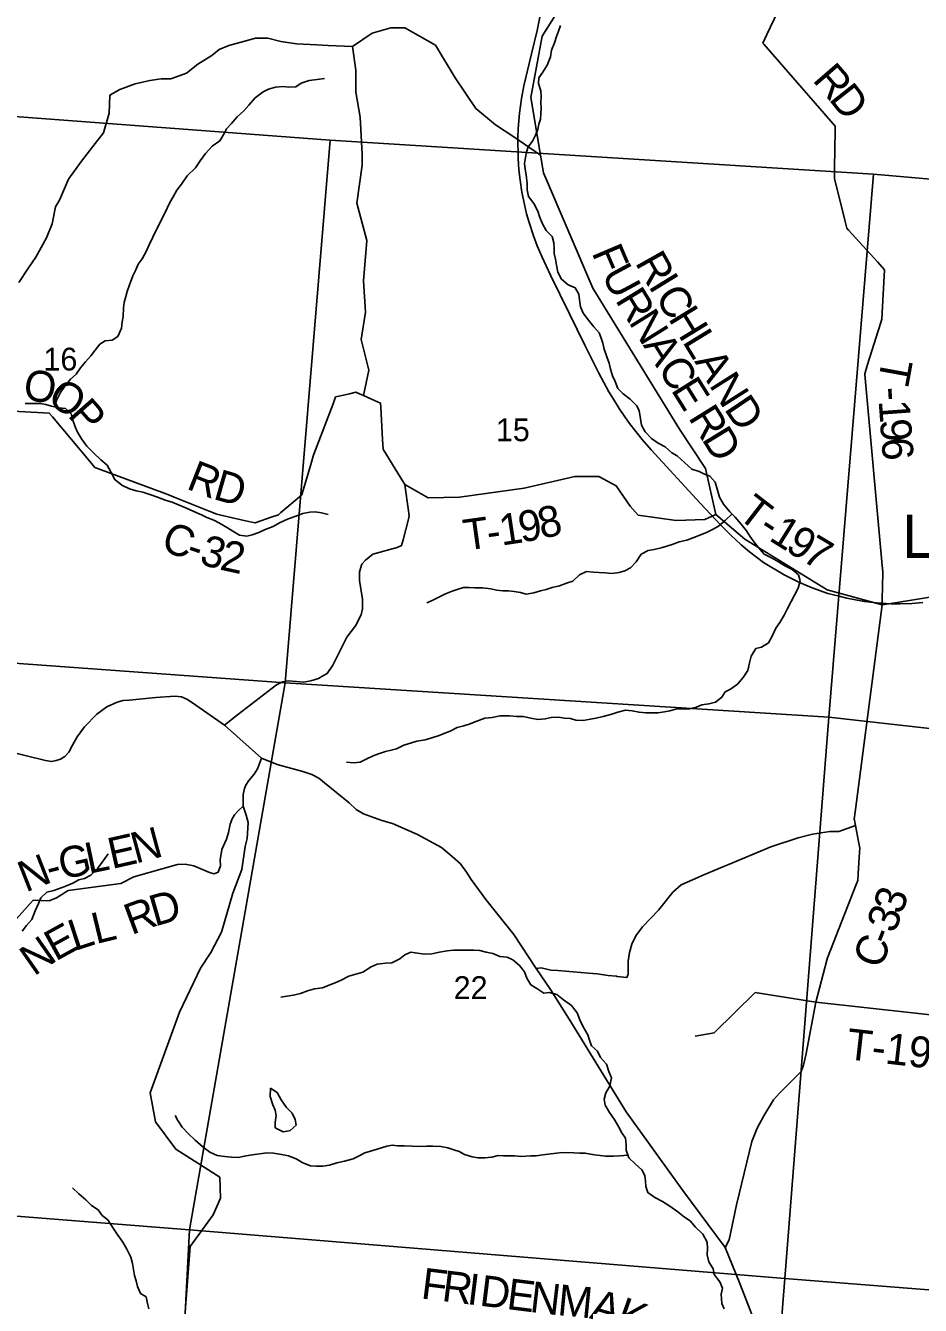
# Model space of a CAD drawing. Extents: x 1715311 to 2083412, y 146837 to 553079.
# Drawn here: x 1938656 to 1947326, y 414870 to 427271 of the extents above; entities that cross this region are included whole.
import ezdxf

# ---------------------------------------------------------------- set-up
doc = ezdxf.new("R2010")
doc.units = 0
for name, color, linetype in [('GM_X_County_Road', 7, 'Continuous'), ('GM_X_County_Road_Text', 7, 'Continuous'), ('GM_X_Minor_Lake', 7, 'Continuous'), ('GM_X_Minor_River', 7, 'Continuous'), ('GM_X_Rail_Line', 7, 'Continuous'), ('GM_X_Section', 7, 'Continuous'), ('GM_X_Section_Text', 7, 'Continuous'), ('GM_X_State_Route', 7, 'Continuous'), ('GM_X_Township_Road', 7, 'Continuous'), ('GM_X_Township_Road_Text', 7, 'Continuous'), ('GM_X_Township_ROW', 7, 'Continuous'), ('GM_X_Unincorporated_Text', 7, 'Continuous')]:
    doc.layers.add(name, color=color, linetype=linetype)

msp = doc.modelspace()

# ---------------------------------------------------------------- linework, layer by layer
at = {"layer": 'GM_X_County_Road'}
for points in [[(1940582, 420491), (1940708, 420592), (1941089, 420884), (1941146, 420914), (1941202, 420923), (1941280, 420915), (1941349, 420910), (1941421, 420923), (1941493, 420944), (1941542, 420974), (1941579, 420994), (1941634, 421073), (1941769, 421345), (1941853, 421456), (1941908, 421561), (1941918, 421608), (1941920, 421612), (1941920, 421712), (1941893, 421894), (1941893, 421978), (1941915, 422052), (1941949, 422091), (1942020, 422151), (1942256, 422215), (1942300, 422233), (1942314, 422288), (1942365, 422490), (1942372, 422521), (1942362, 422593), (1942334, 422800), (1942330, 422824), (1942288, 422892), (1942125, 423159), (1942120, 423166), (1942115, 423262), (1942098, 423574), (1942096, 423613), (1942036, 423639), (1941931, 423686), (1941893, 423703), (1941856, 423719), (1941794, 423704), (1941692, 423681), (1941660, 423673), (1941635, 423607), (1941449, 423119), (1941442, 423100), (1941419, 423019), (1941347, 422769), (1941334, 422726), (1941289, 422687), (1941130, 422552), (1941106, 422531), (1941037, 422507), (1940890, 422456), (1940882, 422453), (1940788, 422474), (1940534, 422532), (1940510, 422537), (1940436, 422567), (1940096, 422701), (1940050, 422720), (1939999, 422739), (1939364, 422976), (1939328, 422990), (1939286, 423040), (1938917, 423480), (1938886, 423517), (1938830, 423520), (1938413, 423541)], [(1947021, 421668), (1948875, 421968), (1949320, 421983), (1949558, 421879), (1950033, 421640), (1952911, 421117), (1953079, 421207), (1954316, 420828), (1954510, 421266), (1954816, 421770), (1955712, 421936), (1956245, 422267), (1957485, 422207), (1957564, 422217)], [(1945436, 415430), (1945472, 415507), (1945543, 415846), (1945693, 416458), (1945746, 416587), (1945809, 416706), (1945902, 416861), (1945962, 416927), (1946171, 417136), (1946194, 417199), (1946221, 417310), (1946314, 417807), (1946419, 418215), (1946425, 418239), (1946454, 418314), (1946705, 418950), (1946719, 418986), (1946723, 419052), (1946736, 419262), (1946739, 419301), (1946726, 419366), (1946697, 419521), (1946687, 419572), (1946685, 419583), (1946697, 419677), (1946956, 421658), (1947021, 421668)]]:
    msp.add_lwpolyline(points, dxfattribs=at)
at = {"layer": 'GM_X_Minor_Lake'}
for points in [[(1941030, 416975), (1941026, 416895), (1941051, 416813), (1941073, 416761), (1941085, 416711), (1941075, 416641), (1941075, 416591), (1941151, 416553), (1941191, 416560)], [(1941191, 416560), (1941221, 416565), (1941277, 416617), (1941269, 416671), (1941239, 416733), (1941183, 416787), (1941133, 416861), (1941094, 416933), (1941030, 416975)]]:
    msp.add_lwpolyline(points, dxfattribs=at)
at = {"layer": 'GM_X_Minor_River'}
for points in [[(1943839, 427273), (1943819, 427217), (1943799, 427165), (1943781, 427103), (1943751, 427033), (1943743, 426969), (1943711, 426889), (1943669, 426821), (1943629, 426765), (1943625, 426709), (1943650, 426640), (1943652, 426586), (1943648, 426524), (1943652, 426472), (1943648, 426416), (1943644, 426366), (1943630, 426316), (1943620, 426266), (1943598, 426210), (1943569, 426152), (1943525, 426096), (1943511, 426044), (1943501, 425994), (1943491, 425934), (1943497, 425880), (1943505, 425824), (1943515, 425742), (1943517, 425680), (1943528, 425614), (1943580, 425548), (1943620, 425474), (1943636, 425420), (1943664, 425349), (1943699, 425287), (1943759, 425227), (1943773, 425167), (1943779, 425113), (1943779, 425063), (1943791, 425007), (1943799, 424951), (1943813, 424881)], [(1938935, 423578), (1938956, 423638), (1938996, 423716), (1939037, 423778), (1939093, 423844), (1939145, 423894), (1939187, 423954), (1939237, 424014), (1939287, 424072), (1939329, 424126), (1939377, 424184), (1939427, 424216), (1939495, 424224), (1939551, 424260), (1939585, 424340), (1939593, 424400), (1939601, 424454), (1939605, 424538), (1939613, 424588), (1939626, 424646), (1939640, 424696), (1939662, 424760), (1939696, 424846), (1939724, 424904), (1939746, 424958), (1939786, 425010), (1939824, 425082), (1939854, 425146), (1939888, 425222), (1939927, 425302), (1939969, 425382), (1940029, 425502), (1940053, 425556), (1940087, 425613), (1940123, 425677), (1940167, 425735), (1940223, 425815), (1940301, 425893), (1940347, 425961), (1940401, 426033), (1940463, 426103), (1940537, 426153), (1940576, 426219), (1940602, 426271), (1940652, 426323), (1940706, 426387), (1940772, 426445), (1940820, 426501), (1940882, 426571), (1940958, 426630), (1941010, 426654), (1941078, 426674), (1941152, 426680), (1941206, 426676), (1941276, 426678), (1941326, 426712), (1941404, 426740), (1941483, 426749), (1941553, 426757)], [(1943813, 424881), (1943848, 424815), (1943914, 424760), (1943982, 424730), (1944018, 424670), (1944024, 424614), (1944034, 424546), (1944059, 424484), (1944111, 424418), (1944161, 424351), (1944215, 424293), (1944233, 424243), (1944249, 424193), (1944262, 424135), (1944288, 424063), (1944310, 424001), (1944324, 423943), (1944344, 423877), (1944368, 423821), (1944395, 423754), (1944445, 423702), (1944513, 423650), (1944577, 423590), (1944601, 423540), (1944613, 423460), (1944624, 423400), (1944658, 423335), (1944722, 423269), (1944786, 423225), (1944852, 423189), (1944917, 423133), (1944969, 423103), (1945113, 422974), (1945183, 422950), (1945235, 422926), (1945286, 422904), (1945338, 422848), (1945362, 422769), (1945380, 422701), (1945420, 422635), (1945481, 422561), (1945533, 422507), (1945589, 422439), (1945641, 422376), (1945673, 422324), (1945715, 422266), (1945754, 422216), (1945814, 422148), (1945884, 422114), (1945950, 422075), (1946018, 422033), (1946084, 422001), (1946145, 421949), (1946161, 421891), (1946141, 421819), (1946107, 421751), (1946073, 421691), (1946037, 421617), (1946005, 421559), (1945963, 421487), (1945927, 421431), (1945890, 421355), (1945856, 421289), (1945788, 421247), (1945732, 421235), (1945688, 421161), (1945672, 421097), (1945654, 421023), (1945608, 420955), (1945554, 420891), (1945486, 420843), (1945434, 420815), (1945404, 420763), (1945342, 420716), (1945278, 420698), (1945208, 420690), (1945156, 420668), (1945090, 420650), (1945038, 420648), (1944968, 420650), (1944898, 420630), (1944846, 420621), (1944782, 420611), (1944730, 420611), (1944667, 420613), (1944601, 420617), (1944535, 420631), (1944469, 420637), (1944395, 420620), (1944335, 420598), (1944253, 420576), (1944183, 420560), (1944129, 420552), (1944059, 420538), (1943989, 420542), (1943935, 420556), (1943876, 420559), (1943822, 420571), (1943750, 420567), (1943692, 420553), (1943620, 420549)], [(1938653, 423611), (1938727, 423609), (1938802, 423609), (1938854, 423600), (1938908, 423584), (1938978, 423568), (1939044, 423560), (1939098, 423508), (1939110, 423458), (1939138, 423382), (1939159, 423332), (1939197, 423267), (1939251, 423197), (1939313, 423131), (1939385, 423065)], [(1939385, 423065), (1939446, 423013), (1939484, 422940), (1939520, 422872), (1939590, 422818), (1939662, 422782), (1939728, 422762), (1939793, 422750), (1939869, 422725), (1939935, 422701), (1940017, 422669), (1940077, 422653), (1940137, 422627), (1940217, 422595), (1940286, 422562), (1940360, 422532), (1940414, 422506), (1940480, 422478), (1940534, 422450), (1940612, 422404), (1940665, 422371), (1940729, 422335), (1940799, 422325), (1940853, 422337), (1940915, 422361), (1940979, 422387), (1941055, 422419), (1941115, 422452), (1941195, 422490), (1941265, 422514), (1941343, 422544), (1941411, 422558), (1941463, 422560), (1941523, 422550), (1941587, 422533)], [(1945501, 422540), (1945435, 422475), (1945369, 422421), (1945311, 422389), (1945259, 422363), (1945189, 422333), (1945131, 422311), (1945063, 422286), (1944988, 422268), (1944920, 422244), (1944868, 422226), (1944816, 422212), (1944746, 422194), (1944690, 422184), (1944622, 422148), (1944572, 422076), (1944516, 422017), (1944462, 421987), (1944408, 421971), (1944336, 421963), (1944272, 421969), (1944210, 421971), (1944158, 421975), (1944090, 421981), (1944022, 421948), (1943960, 421888), (1943898, 421868), (1943830, 421844), (1943758, 421826), (1943700, 421806), (1943646, 421794), (1943582, 421774), (1943508, 421763), (1943451, 421779), (1943391, 421787), (1943335, 421793), (1943281, 421793), (1943219, 421801), (1943165, 421813), (1943085, 421824), (1943009, 421824), (1942953, 421826), (1942899, 421826), (1942847, 421810), (1942791, 421792), (1942726, 421764), (1942674, 421740), (1942596, 421702), (1942544, 421679)], [(1943620, 420549), (1943552, 420561), (1943476, 420578), (1943412, 420578), (1943344, 420584), (1943256, 420584), (1943178, 420568), (1943105, 420562), (1943027, 420530), (1942953, 420503), (1942901, 420487), (1942839, 420469), (1942769, 420433), (1942717, 420415), (1942663, 420391), (1942593, 420371), (1942527, 420351), (1942447, 420336), (1942395, 420320), (1942321, 420298), (1942249, 420264), (1942197, 420250), (1942143, 420236), (1942075, 420216), (1942023, 420194), (1941969, 420168), (1941897, 420133), (1941833, 420129), (1941767, 420135)], [(1938622, 418498), (1938664, 418550), (1938718, 418610), (1938750, 418692), (1938780, 418766), (1938805, 418818), (1938863, 418876), (1938931, 418892), (1939038, 418928), (1939114, 418962), (1939172, 418993), (1939228, 419007), (1939288, 419039), (1939356, 419107), (1939407, 419179), (1939457, 419247)], [(1945424, 414838), (1945404, 414890), (1945396, 414980), (1945410, 415036), (1945384, 415100), (1945328, 415170), (1945319, 415224), (1945277, 415291), (1945261, 415359), (1945265, 415421), (1945261, 415483), (1945217, 415561), (1945148, 415627), (1945096, 415689), (1945042, 415724), (1944976, 415778), (1944900, 415832), (1944827, 415878), (1944753, 415916), (1944687, 415963), (1944667, 416021), (1944663, 416073), (1944655, 416129), (1944627, 416185), (1944562, 416243), (1944502, 416301), (1944476, 416373), (1944476, 416427), (1944468, 416490), (1944432, 416544), (1944405, 416596), (1944365, 416666), (1944315, 416738), (1944273, 416810), (1944261, 416868), (1944279, 416930), (1944318, 416994), (1944332, 417074), (1944306, 417138), (1944286, 417209), (1944228, 417271), (1944198, 417333), (1944141, 417385), (1944119, 417441), (1944103, 417493), (1944059, 417569), (1944027, 417638), (1944001, 417704), (1943946, 417776), (1943868, 417832), (1943804, 417884), (1943734, 417902), (1943678, 417897), (1943610, 417941), (1943551, 417975), (1943513, 418041), (1943489, 418101), (1943443, 418165), (1943377, 418220), (1943323, 418244), (1943250, 418252), (1943182, 418280), (1943120, 418294), (1943056, 418310), (1942998, 418314), (1942932, 418311), (1942876, 418311), (1942802, 418313), (1942740, 418305), (1942668, 418293), (1942592, 418277), (1942523, 418273), (1942455, 418284), (1942389, 418292), (1942331, 418268), (1942281, 418228), (1942205, 418190), (1942145, 418188), (1942063, 418176), (1942005, 418152), (1941925, 418099), (1941857, 418081), (1941787, 418059), (1941709, 418019), (1941657, 417995), (1941603, 417977)], [(1941603, 417977), (1941533, 417949), (1941457, 417939), (1941389, 417918), (1941319, 417892), (1941251, 417876), (1941189, 417866), (1941130, 417856)], [(1944494, 416325), (1944410, 416319), (1944354, 416316), (1944276, 416316), (1944224, 416322), (1944170, 416330), (1944075, 416346), (1944023, 416346), (1943967, 416350), (1943855, 416351), (1943799, 416345), (1943745, 416339), (1943667, 416329), (1943605, 416321), (1943551, 416319), (1943457, 416314), (1943395, 416320), (1943341, 416320), (1943288, 416318), (1943236, 416322), (1943174, 416308), (1943106, 416300), (1943042, 416300), (1942984, 416311), (1942910, 416333), (1942858, 416363), (1942806, 416379), (1942746, 416397), (1942679, 416411), (1942603, 416412), (1942541, 416414), (1942463, 416410), (1942403, 416412), (1942329, 416416), (1942261, 416418), (1942209, 416422), (1942157, 416414), (1942063, 416385), (1941999, 416365), (1941943, 416349), (1941889, 416321), (1941831, 416291), (1941747, 416269), (1941672, 416253), (1941602, 416230), (1941536, 416220), (1941472, 416220), (1941418, 416224), (1941344, 416252), (1941278, 416292), (1941204, 416320), (1941136, 416333), (1941057, 416345), (1940995, 416349), (1940855, 416329), (1940791, 416321), (1940719, 416304), (1940651, 416306), (1940587, 416314), (1940511, 416324), (1940443, 416354), (1940376, 416404), (1940300, 416471), (1940230, 416537), (1940174, 416597), (1940130, 416661), (1940104, 416711)], [(1939851, 414838), (1939839, 414888), (1939823, 414952), (1939769, 414986), (1939742, 415052), (1939728, 415109), (1939712, 415161), (1939702, 415217), (1939692, 415277), (1939676, 415339), (1939636, 415415), (1939599, 415483), (1939549, 415551), (1939505, 415618), (1939453, 415698), (1939399, 415742), (1939360, 415796), (1939296, 415838), (1939240, 415892), (1939172, 415951), (1939112, 416009)]]:
    msp.add_lwpolyline(points, dxfattribs=at)
at = {"layer": 'GM_X_Rail_Line'}
msp.add_lwpolyline([(1943640, 427353), (1943614, 427223), (1943558, 426996), (1943484, 426689), (1943460, 426565), (1943441, 426424), (1943428, 426275), (1943425, 426191), (1943429, 425985), (1943437, 425875), (1943448, 425772), (1943466, 425657), (1943490, 425537), (1943510, 425448), (1943534, 425363), (1943576, 425234), (1943613, 425136), (1943657, 425033), (1943743, 424852), (1943927, 424477), (1944076, 424174), (1944212, 423902), (1944308, 423723), (1944352, 423650), (1944409, 423560), (1944461, 423481), (1944507, 423417), (1944570, 423338), (1944632, 423262), (1944718, 423161), (1945193, 422643), (1945392, 422430), (1945489, 422334), (1945590, 422239), (1945671, 422172), (1945806, 422069), (1946005, 421950), (1946156, 421874), (1946278, 421823), (1946430, 421770), (1946539, 421741), (1946614, 421722), (1946699, 421706), (1946786, 421691), (1946901, 421677), (1947041, 421669), (1947126, 421669), (1947243, 421671), (1947350, 421680)], dxfattribs=at)
at = {"layer": 'GM_X_Section'}
for points in [[(1941609, 426162), (1941173, 420902), (1936233, 421261), (1936827, 426520)], [(1946873, 425833), (1946438, 420569), (1941173, 420902), (1941609, 426162)], [(1952432, 425343), (1951964, 419951), (1946438, 420569), (1946873, 425833)], [(1936233, 421261), (1941173, 420902), (1940243, 415602), (1935665, 415965)], [(1946438, 420569), (1946012, 415130), (1940243, 415602), (1941173, 420902)], [(1946438, 420569), (1951964, 419951), (1951464, 414700), (1946012, 415130)], [(1940243, 415602), (1939970, 410322), (1935235, 410505), (1935665, 415965)], [(1940243, 415602), (1946012, 415130), (1945608, 410066), (1939970, 410322)], [(1951464, 414700), (1950968, 409489), (1945608, 410066), (1946012, 415130)]]:
    msp.add_lwpolyline(points, close=True, dxfattribs=at)
at = {"layer": 'GM_X_State_Route'}
msp.add_lwpolyline([(1945799, 414507), (1945578, 415081), (1945436, 415430), (1945025, 415984), (1944474, 416745), (1943939, 417619), (1943743, 417932), (1943602, 418135), (1943386, 418463), (1943117, 418803), (1942973, 418997), (1942930, 419069), (1942869, 419149), (1942790, 419221), (1942687, 419308), (1942453, 419432), (1942211, 419539), (1942109, 419570), (1942000, 419606), (1941931, 419635), (1941859, 419675), (1941790, 419741), (1941554, 419933), (1941499, 419979), (1941430, 420014), (1941344, 420043), (1941093, 420111), (1940943, 420172), (1940582, 420491), (1940273, 420710), (1940218, 420745), (1940166, 420766), (1940102, 420773), (1939917, 420761), (1939661, 420736), (1939602, 420732), (1939542, 420715), (1939444, 420670), (1939348, 420599), (1939228, 420478), (1939156, 420380), (1939112, 420300), (1939074, 420230), (1939037, 420188), (1938993, 420163), (1938952, 420149), (1938908, 420140), (1938850, 420151), (1938083, 420339)], dxfattribs=at)
at = {"layer": 'GM_X_Township_Road'}
for points in [[(1946956, 421658), (1946422, 421803), (1945624, 422296), (1945343, 422533), (1945243, 422979), (1944992, 423362), (1944153, 424726), (1943674, 425846), (1943644, 426016), (1943551, 426574), (1943662, 427169), (1943959, 427643), (1944005, 428059), (1943905, 428416), (1943866, 428844), (1943419, 429503), (1943119, 429621)], [(1946956, 421658), (1946957, 421710), (1946963, 421970), (1946963, 421976), (1946954, 422074), (1946788, 423889), (1946787, 423897), (1946815, 423988), (1946940, 424386), (1946953, 424426), (1946956, 424488), (1946979, 424904), (1946979, 424906), (1946911, 424981), (1946631, 425290), (1946615, 425307), (1946595, 425385), (1946493, 425789), (1946493, 425790), (1946494, 425893), (1946500, 426258), (1946501, 426296), (1946458, 426346), (1945809, 427092), (1945801, 427101), (1945840, 427184), (1946016, 427561)], [(1942330, 422824), (1942558, 422694), (1942860, 422701), (1943487, 422789), (1943978, 422903), (1944212, 422903), (1944380, 422812), (1944515, 422616), (1944593, 422526), (1944961, 422475), (1945238, 422486), (1945343, 422533)], [(1940192, 414682), (1940250, 415441), (1940474, 415747), (1940544, 415909), (1940537, 416112), (1940112, 416383), (1939914, 416648), (1939864, 416931), (1940149, 417713), (1940351, 418139), (1940451, 418289), (1940553, 418488), (1940665, 418864), (1940751, 419094), (1940785, 419317), (1940803, 419396), (1940807, 419444), (1940812, 419549), (1940794, 419619), (1940766, 419707), (1940765, 419821), (1940776, 419880), (1940790, 419911), (1940820, 419958), (1940870, 420018), (1940903, 420069), (1940943, 420172)], [(1940766, 419707), (1940716, 419662), (1940680, 419624), (1940657, 419586), (1940639, 419534), (1940623, 419451), (1940603, 419387), (1940558, 419288), (1940540, 419188), (1940544, 419129), (1940522, 419067), (1940484, 419052), (1940439, 419064), (1940287, 419128), (1940202, 419145), (1940127, 419141), (1939704, 419022), (1939580, 418960), (1939069, 418889), (1938957, 418820), (1938884, 418792), (1938730, 418796), (1938153, 418155)], [(1945429, 419126), (1945459, 419139), (1945877, 419314), (1946141, 419402), (1946281, 419437), (1946448, 419463), (1946536, 419463), (1946697, 419521)], [(1943602, 418135), (1943651, 418141), (1943747, 418119), (1943813, 418114), (1944110, 418088), (1944194, 418084), (1944302, 418068), (1944383, 418059), (1944387, 418058)], [(1946314, 417807), (1948245, 417596), (1948342, 417994), (1949239, 418062), (1949409, 418020)], [(1945145, 417478), (1945329, 417513), (1945725, 417901), (1946314, 417807)]]:
    msp.add_lwpolyline(points, dxfattribs=at)
at = {"layer": 'GM_X_Township_ROW'}
for points in [[(1941931, 423686), (1941983, 423933), (1941909, 424229), (1941951, 424493), (1941930, 424799), (1941962, 425190), (1941867, 425549), (1941919, 425919), (1941919, 426025), (1941898, 426384), (1941856, 426627), (1941856, 426838), (1941824, 427070), (1942014, 427197), (1942194, 427250), (1942331, 427250), (1942627, 427081), (1942817, 426764), (1943018, 426468), (1943208, 426310), (1943387, 426193), (1943644, 426016)], [(1938590, 424782), (1938685, 424924), (1938756, 425026), (1938858, 425216), (1938914, 425350), (1938945, 425515), (1938985, 425579), (1939071, 425784), (1939198, 425957), (1939308, 426099), (1939410, 426233), (1939466, 426423), (1939474, 426596), (1939568, 426651), (1939718, 426706), (1939860, 426738), (1939970, 426754), (1940065, 426754), (1940215, 426809), (1940325, 426896), (1940460, 426982), (1940531, 427038), (1940625, 427077), (1940767, 427117), (1940885, 427148), (1941004, 427148), (1941130, 427117), (1941280, 427093), (1941477, 427085), (1941587, 427077), (1941824, 427070)], [(1944387, 418058), (1944482, 418048), (1944494, 418079), (1944495, 418207), (1944507, 418291), (1944530, 418370), (1944569, 418450), (1944633, 418537), (1944789, 418700), (1944929, 418875), (1945008, 418945), (1945228, 419042), (1945429, 419126)]]:
    msp.add_lwpolyline(points, dxfattribs=at)

# ---------------------------------------------------------------- texts
at = {"layer": 'GM_X_County_Road_Text'}
for s, rotation, p in [('O', 351.6576, (1938623, 423650)), ('O', 326.4271, (1938852, 423625)), ('P', 311.3388, (1939056, 423492)), ('R', 338.5559, (1940204, 422787)), ('D', 344.1455, (1940463, 422687)), ('C', 338.6436, (1939954, 422197)), ('3', 344.1538, (1940330, 422057)), ('2', 347.685, (1940528, 422002)), ('-', 340.9985, (1940197, 422103)), ('3', 70.9493, (1947145, 418648)), ('3', 69.3167, (1947077, 418467)), ('C', 68.7277, (1946942, 418119)), ('-', 68.8517, (1947032, 418349))]:
    msp.add_text(s, height=300, rotation=rotation, dxfattribs=at).set_placement(p)
at = {"layer": 'GM_X_Section_Text'}
for s, p in [('16', (1938829, 423929)), ('15', (1943213, 423244)), ('22', (1942804, 417839))]:
    msp.add_text(s, height=221, rotation=0, dxfattribs=at).set_placement(p)
at = {"layer": 'GM_X_Township_Road_Text'}
for s, rotation, p in [('R', 310.9341, (1946273, 426741)), ('D', 308.2849, (1946432, 426558)), ('F', 293.1081, (1944138, 425072)), ('R', 299.3344, (1944557, 424975)), ('U', 298.3757, (1944230, 424859)), ('I', 301.5595, (1944685, 424749)), ('R', 301.4465, (1944364, 424612)), ('C', 301.4792, (1944749, 424644)), ('N', 301.9368, (1944494, 424399)), ('H', 301.4768, (1944878, 424434)), ('A', 301.9477, (1944634, 424175)), ('L', 301.4769, (1945015, 424209)), ('C', 301.9437, (1944774, 423951)), ('A', 301.4779, (1945133, 424018)), ('T', 259.672, (1946958, 424061)), ('E', 301.9489, (1944904, 423742)), ('N', 302.2829, (1945273, 423789)), ('-', 273.5028, (1946913, 423762)), ('D', 303.8813, (1945419, 423558)), ('1', 274.2104, (1946921, 423636)), ('R', 301.9264, (1945072, 423473)), ('D', 301.4304, (1945202, 423265)), ('9', 274.3164, (1946934, 423452)), ('6', 274.3162, (1946948, 423270)), ('8', 12.9134, (1943657, 422296)), ('T', 322.2864, (1945541, 422512)), ('T', 7.8677, (1942919, 422184)), ('1', 8.6098, (1943268, 422232)), ('9', 9.8772, (1943458, 422261)), ('-', 327.0089, (1945741, 422360)), ('1', 328.1387, (1945848, 422290)), ('9', 328.3329, (1946005, 422192)), ('-', 8.0234, (1943143, 422214)), ('7', 329.0834, (1946165, 422094)), ('E', 12.7405, (1939492, 419098)), ('N', 15.0408, (1939723, 419150)), ('G', 12.5067, (1939010, 418994)), ('L', 11.7873, (1939267, 419051)), ('N', 21.384, (1938657, 418870)), ('-', 14.5588, (1938893, 418964)), ('R', 20.3507, (1939682, 418457)), ('D', 16.0059, (1939908, 418541)), ('L', 13.5747, (1939338, 418371)), ('E', 28.6508, (1938947, 418201)), ('L', 18.0568, (1939131, 418303)), ('N', 34.8601, (1938738, 418055)), ('T-192', 353.5045, (1946600, 417258)), ('F', 352.9215, (1942480, 414939)), ('R', 352.9212, (1942681, 414914)), ('I', 352.922, (1942925, 414884)), ('D', 352.9188, (1943047, 414869)), ('E', 352.9237, (1943309, 414836)), ('N', 353.2842, (1943534, 414808)), ('M', 354.4292, (1943803, 414777)), ('A', 343.4592, (1944112, 414748)), ('K', 340.6446, (1944361, 414674))]:
    msp.add_text(s, height=300, rotation=rotation, dxfattribs=at).set_placement(p)
at = {"layer": 'GM_X_Unincorporated_Text'}
msp.add_text('Lesmil', height=417, rotation=0, dxfattribs=at).set_placement((1947151, 422114))

doc.saveas('drawing.dxf')
